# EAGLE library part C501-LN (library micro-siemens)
MICROPROCESSOR/PERIPHERAL DEVICE
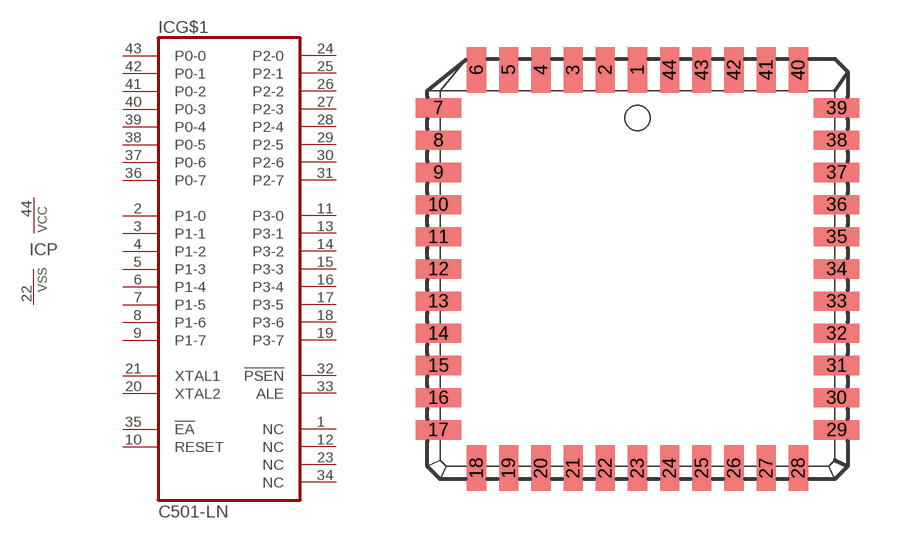
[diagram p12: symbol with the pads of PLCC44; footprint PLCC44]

Designator prefix IC; gates G$1=C501-LN P=VCCVSS

## C501-LN (OC_FARNELL: unknown; OC_NEWARK: unknown)  [PLCC44]
1  G$1:NC  nc
2  G$1:P1-0
3  G$1:P1-1
4  G$1:P1-2
5  G$1:P1-3
6  G$1:P1-4
7  G$1:P1-5
8  G$1:P1-6
9  G$1:P1-7
10  G$1:RESET  in
11  G$1:P3-0
12  G$1:NC  nc
13  G$1:P3-1
14  G$1:P3-2
15  G$1:P3-3
16  G$1:P3-4
17  G$1:P3-5
18  G$1:P3-6
19  G$1:P3-7
20  G$1:XTAL2  pas
21  G$1:XTAL1  pas
22  P:VSS  pwr
23  G$1:NC  nc
24  G$1:P2-0
25  G$1:P2-1
26  G$1:P2-2
27  G$1:P2-3
28  G$1:P2-4
29  G$1:P2-5
30  G$1:P2-6
31  G$1:P2-7
32  G$1:!PSEN  out
33  G$1:ALE  out
34  G$1:NC  nc
35  G$1:!EA  in
36  G$1:P0-7
37  G$1:P0-6
38  G$1:P0-5
39  G$1:P0-4
40  G$1:P0-3
41  G$1:P0-2
42  G$1:P0-1
43  G$1:P0-0
44  P:VCC  pwr

## Footprint PLCC44 (pad centres in mm)
PLASTIC LEADED CHIP CARRIER square
smd 0.76 x 1.8: 1 0,7.86; 2 -1.27,7.86; 3 -2.54,7.86; 4 -3.81,7.86; 5 -5.08,7.86; 6 -6.35,7.86; 18 -6.35,-7.86; 19 -5.08,-7.86; 20 -3.81,-7.86; 21 -2.54,-7.86; 22 -1.27,-7.86; 23 0,-7.86; 24 1.27,-7.86; 25 2.54,-7.86; 26 3.81,-7.86; 27 5.08,-7.86; 28 6.35,-7.86; 40 6.35,7.86; 41 5.08,7.86; 42 3.81,7.86; 43 2.54,7.86; 44 1.27,7.86
smd 1.8 x 0.76: 7 -7.86,6.35; 8 -7.86,5.08; 9 -7.86,3.81; 10 -7.86,2.54; 11 -7.86,1.27; 12 -7.86,0; 13 -7.86,-1.27; 14 -7.86,-2.54; 15 -7.86,-3.81; 16 -7.86,-5.08; 17 -7.86,-6.35; 29 7.86,-6.35; 30 7.86,-5.08; 31 7.86,-3.81; 32 7.86,-2.54; 33 7.86,-1.27; 34 7.86,0; 35 7.86,1.27; 36 7.86,2.54; 37 7.86,3.81; 38 7.86,5.08; 39 7.86,6.35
